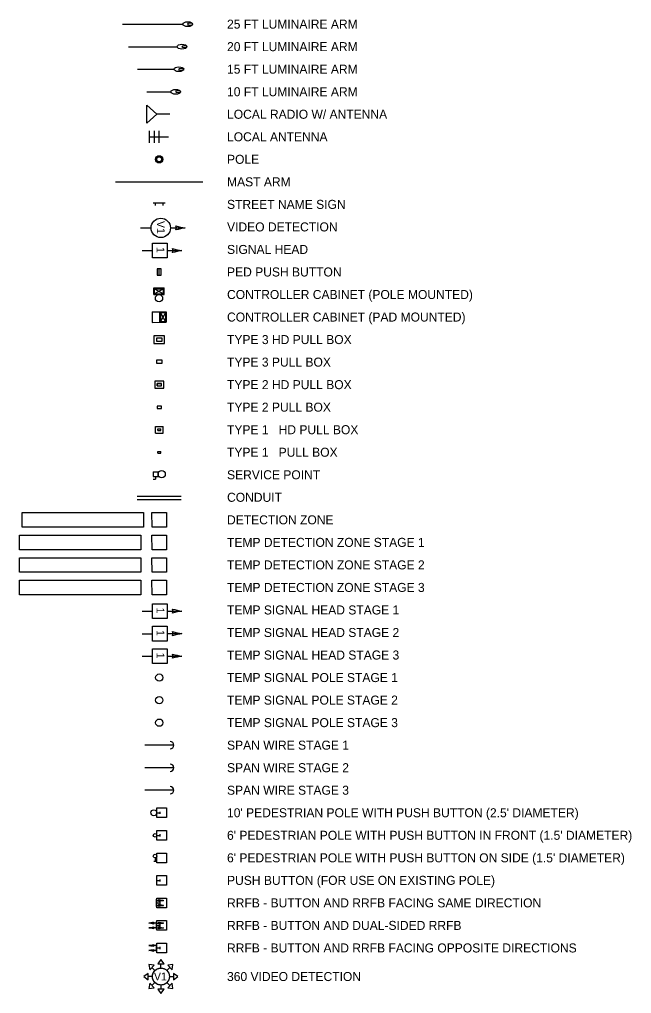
# Model space of a CAD drawing. Extents: x 995948 to 996893, y 1982239 to 1983420.
# Drawn here: x 995947.9 to 996200.4, y 1983017.7 to 1983419.7 of the extents above; entities that cross this region are included whole.
import ezdxf

# ---------------------------------------------------------------- set-up
doc = ezdxf.new("R2010")
doc.units = 0
for name, color, linetype in [('_CIVIL_CONSTRUCTION', 7, 'Continuous'), ('DSN_RDWY_Alignment Annotation', 7, 'Continuous'), ('DSN_ROW_Line-Annotation', 7, 'Continuous'), ('DSN_ROW_Point', 7, 'Continuous'), ('EX_ALIGNMENT', 7, 'Continuous'), ('EX_ROW', 7, 'Continuous'), ('S_CROSS_DRAIN', 7, 'Continuous'), ('S_CURB', 7, 'Continuous'), ('S_DRIVEWAY', 7, 'Continuous'), ('S_EDGE_PAVEMENT', 7, 'Continuous'), ('S_HWY_SYMBOLS', 7, 'Continuous'), ('S_HWY_TEXT', 7, 'Continuous'), ('S_ORTHO_IMAGE', 7, 'Continuous'), ('S_PARKING', 7, 'Continuous'), ('S_PAVEMENT_CROWN', 7, 'Continuous'), ('S_SHOULDER', 7, 'Continuous'), ('S_SIDE_DRAIN', 7, 'Continuous'), ('S_SIDEWALK', 7, 'Continuous'), ('S_WALL', 7, 'Continuous'), ('S_WALL_ANNOT', 7, 'Continuous')]:
    doc.layers.add(name, color=color, linetype=linetype)

msp = doc.modelspace()

# ---------------------------------------------------------------- linework, layer by layer
at = {"layer": '_CIVIL_CONSTRUCTION'}
for p, q in [((995947.87, 1983188.24), (995997.87, 1983188.27)), ((995947.87, 1983182.24), (995947.87, 1983188.24)), ((995997.87, 1983188.27), (995997.87, 1983182.27)), ((995997.87, 1983182.27), (995947.87, 1983182.24))]:
    msp.add_line(p, q, dxfattribs=at)
msp.add_lwpolyline([(996008.55, 1983182.27), (996002.55, 1983182.27), (996002.54, 1983188.27), (996008.54, 1983188.27)], close=True, dxfattribs=at)
at = {"layer": 'DSN_RDWY_Alignment Annotation'}
for p, q in [((995998.43, 1983166.2), (996002.78, 1983166.2)), ((996008.84, 1983166.23), (996014.88, 1983166.23))]:
    msp.add_line(p, q, dxfattribs=at)
msp.add_lwpolyline([(996002.78, 1983163.18), (996002.78, 1983169.25), (996008.84, 1983169.25), (996008.84, 1983163.18)], close=True, dxfattribs=at)
for centre, radius, start, end in [((996009.62, 1983166.22), 1.63, 328.1778, 31.8725), ((996019.28, 1983195.37), 29.47, 253.6787, 261.4168), ((996019.31, 1983137.09), 29.47, 98.6335, 106.3716)]:
    msp.add_arc(centre, radius, start, end, dxfattribs=at)
at = {"layer": 'DSN_ROW_Line-Annotation'}
for p, q in [((996008.84, 1983175.53), (996014.88, 1983175.53)), ((995998.43, 1983175.5), (996002.78, 1983175.5))]:
    msp.add_line(p, q, dxfattribs=at)
msp.add_lwpolyline([(996002.78, 1983172.48), (996002.78, 1983178.55), (996008.84, 1983178.55), (996008.84, 1983172.48)], close=True, dxfattribs=at)
for centre, radius, start, end in [((996009.62, 1983175.52), 1.63, 328.1778, 31.8725), ((996019.28, 1983204.67), 29.47, 253.6787, 261.4168), ((996019.31, 1983146.39), 29.47, 98.6335, 106.3716)]:
    msp.add_arc(centre, radius, start, end, dxfattribs=at)
at = {"layer": 'DSN_ROW_Point'}
for p, q in [((995998.43, 1983156.9), (996002.78, 1983156.9)), ((996008.84, 1983156.93), (996014.88, 1983156.93))]:
    msp.add_line(p, q, dxfattribs=at)
msp.add_lwpolyline([(996002.78, 1983153.88), (996002.78, 1983159.95), (996008.84, 1983159.95), (996008.84, 1983153.88)], close=True, dxfattribs=at)
for centre, radius, start, end in [((996009.62, 1983156.92), 1.63, 328.1778, 31.8725), ((996019.28, 1983186.07), 29.47, 253.6787, 261.4168), ((996019.31, 1983127.79), 29.47, 98.6335, 106.3716)]:
    msp.add_arc(centre, radius, start, end, dxfattribs=at)
at = {"layer": 'EX_ALIGNMENT'}
msp.add_line((996011.54, 1983101.58), (995999.54, 1983101.57), dxfattribs=at)
msp.add_circle((996005.54, 1983129.47), 1.5, dxfattribs=at)
msp.add_arc((996010.04, 1983101.58), 1.5, 270.0252, 90.0252, dxfattribs=at)
at = {"layer": 'EX_ROW'}
msp.add_line((996011.54, 1983110.88), (995999.54, 1983110.87), dxfattribs=at)
msp.add_circle((996005.54, 1983138.77), 1.5, dxfattribs=at)
msp.add_arc((996010.04, 1983110.88), 1.5, 270.0252, 90.0252, dxfattribs=at)
at = {"layer": 'S_CROSS_DRAIN'}
msp.add_lwpolyline([(996004.64, 1983316.79), (996004.64, 1983314.15), (996005.51, 1983314.15), (996005.51, 1983316.79)], close=True, dxfattribs=at)
at = {"layer": 'S_CURB'}
for p, q in [((996002.65, 1983299.03), (996008.39, 1983299.04)), ((996002.65, 1983299.03), (996002.65, 1983294.7)), ((996005.65, 1983299.03), (996005.65, 1983294.7)), ((996005.98, 1983298.7), (996008.06, 1983298.71)), ((996005.98, 1983298.7), (996005.98, 1983295.03)), ((996008.06, 1983295.04), (996005.98, 1983298.7)), ((996008.06, 1983298.68), (996005.98, 1983295.03)), ((996008.06, 1983298.71), (996008.06, 1983295.04)), ((996008.39, 1983299.04), (996008.39, 1983294.71)), ((996002.65, 1983294.7), (996008.39, 1983294.71)), ((996005.98, 1983295.03), (996008.06, 1983295.04))]:
    msp.add_line(p, q, dxfattribs=at)
at = {"layer": 'S_DRIVEWAY'}
for p, q in [((996003.03, 1983233.03), (996003.03, 1983231.03)), ((996003.03, 1983233.03), (996005.03, 1983233.03)), ((996005.03, 1983233.03), (996005.03, 1983231.03)), ((996003.03, 1983231.03), (996005.03, 1983231.03)), ((996003.03, 1983230.03), (996004.03, 1983230.03)), ((996004.03, 1983231.03), (996004.03, 1983230.03)), ((995996.47, 1983222.96), (996014.6, 1983222.97)), ((995996.47, 1983221.64), (996014.6, 1983221.65))]:
    msp.add_line(p, q, dxfattribs=at)
msp.add_circle((996006.53, 1983232.03), 1.5, dxfattribs=at)
at = {"layer": 'S_EDGE_PAVEMENT'}
for p, q in [((995987.49, 1983352.67), (996023.49, 1983352.68)), ((996004.3, 1983056.57), (996004.3, 1983053.57)), ((996004.3, 1983056.07), (996007.32, 1983056.07)), ((996004.3, 1983055.19), (996004.3, 1983054.94)), ((996004.3, 1983055.19), (996004.55, 1983055.19)), ((996004.55, 1983054.94), (996004.3, 1983054.94)), ((996004.55, 1983054.94), (996004.55, 1983055.19)), ((996004.3, 1983054.07), (996007.32, 1983054.07)), ((996004.3, 1983047.27), (996004.3, 1983044.27)), ((996004.3, 1983046.77), (996001.28, 1983046.77)), ((996004.3, 1983044.77), (996001.28, 1983044.77)), ((996004.3, 1983046.77), (996007.32, 1983046.77)), ((996004.3, 1983045.89), (996004.3, 1983045.64)), ((996004.3, 1983045.89), (996004.55, 1983045.89)), ((996004.55, 1983045.64), (996004.3, 1983045.64)), ((996004.3, 1983044.77), (996007.32, 1983044.77)), ((996004.55, 1983045.64), (996004.55, 1983045.89)), ((996004.3, 1983037.47), (996001.28, 1983037.47)), ((996004.3, 1983035.47), (996001.28, 1983035.47)), ((996004.3, 1983037.97), (996004.3, 1983034.97)), ((996004.3, 1983036.59), (996004.3, 1983036.34)), ((996004.3, 1983036.59), (996004.55, 1983036.59)), ((996004.55, 1983036.34), (996004.3, 1983036.34)), ((996004.55, 1983036.34), (996004.55, 1983036.59))]:
    msp.add_line(p, q, dxfattribs=at)
for centre, radius in [((996005.48, 1983361.98), 1.5), ((996005.48, 1983361.98), 1.25), ((996005.48, 1983361.98), 1), ((996005.54, 1983148.07), 1.5), ((996003.3, 1983092.27), 1.25), ((996003.8, 1983082.97), 0.75), ((996003.8, 1983074.42), 0.75)]:
    msp.add_circle(centre, radius, dxfattribs=at)
for centre, radius, start, end in [((996004.68, 1983056.07), 0.814, 328.1778, 31.8725), ((996009.51, 1983070.64), 14.74, 253.6787, 261.4168), ((996009.53, 1983041.5), 14.74, 98.6335, 106.3716), ((996004.68, 1983054.07), 0.814, 328.1778, 31.8725), ((996009.52, 1983068.64), 14.74, 253.6787, 261.4168), ((996009.53, 1983039.5), 14.74, 98.6335, 106.3716), ((995999.06, 1983061.34), 14.74, 278.6335, 286.3716), ((996003.91, 1983046.77), 0.814, 148.1778, 211.8725), ((996004.68, 1983046.77), 0.814, 328.1778, 31.8725), ((996009.51, 1983061.34), 14.74, 253.6787, 261.4168), ((995999.08, 1983032.2), 14.74, 73.6787, 81.4168), ((995999.06, 1983059.34), 14.74, 278.6335, 286.3716), ((995999.08, 1983030.2), 14.74, 73.6787, 81.4168), ((996003.91, 1983044.77), 0.814, 148.1778, 211.8725), ((996009.53, 1983032.2), 14.74, 98.6335, 106.3716), ((996004.68, 1983044.77), 0.814, 328.1778, 31.8725), ((996009.52, 1983059.34), 14.74, 253.6787, 261.4168), ((996009.53, 1983030.2), 14.74, 98.6335, 106.3716), ((995999.06, 1983052.04), 14.74, 278.6335, 286.3716), ((995999.08, 1983022.9), 14.74, 73.6787, 81.4168), ((995999.06, 1983050.04), 14.74, 278.6335, 286.3716), ((995999.08, 1983020.9), 14.74, 73.6787, 81.4168), ((996003.91, 1983037.47), 0.814, 148.1778, 211.8725), ((996003.91, 1983035.47), 0.814, 148.1778, 211.8725)]:
    msp.add_arc(centre, radius, start, end, dxfattribs=at)
at = {"layer": 'S_HWY_SYMBOLS'}
for p, q in [((995947.87, 1983197.54), (995997.87, 1983197.57)), ((995947.87, 1983191.54), (995947.87, 1983197.54)), ((995997.87, 1983197.57), (995997.87, 1983191.57)), ((995997.87, 1983191.57), (995947.87, 1983191.54))]:
    msp.add_line(p, q, dxfattribs=at)
msp.add_lwpolyline([(996008.55, 1983191.57), (996002.55, 1983191.57), (996002.54, 1983197.57), (996008.54, 1983197.57)], close=True, dxfattribs=at)
at = {"layer": 'S_HWY_TEXT'}
for p, q in [((995947.87, 1983206.84), (995997.87, 1983206.87)), ((995947.87, 1983200.84), (995947.87, 1983206.84)), ((995997.87, 1983206.87), (995997.87, 1983200.87)), ((995997.87, 1983200.87), (995947.87, 1983200.84))]:
    msp.add_line(p, q, dxfattribs=at)
msp.add_lwpolyline([(996008.55, 1983200.87), (996002.55, 1983200.87), (996002.54, 1983206.87), (996008.54, 1983206.87)], close=True, dxfattribs=at)
at = {"layer": 'S_ORTHO_IMAGE'}
msp.add_line((996011.54, 1983120.18), (995999.54, 1983120.17), dxfattribs=at)
msp.add_arc((996010.04, 1983120.18), 1.5, 270.0252, 90.0252, dxfattribs=at)
at = {"layer": 'S_PARKING'}
for p, q in [((995949.03, 1983216.15), (995999.03, 1983216.17)), ((995949.03, 1983210.15), (995949.03, 1983216.15)), ((995999.03, 1983216.17), (995999.03, 1983210.17)), ((995999.03, 1983210.17), (995949.03, 1983210.15))]:
    msp.add_line(p, q, dxfattribs=at)
msp.add_lwpolyline([(996008.55, 1983210.17), (996002.55, 1983210.17), (996002.54, 1983216.17), (996008.54, 1983216.17)], close=True, dxfattribs=at)
at = {"layer": 'S_PAVEMENT_CROWN'}
for p, q in [((995997.84, 1983333.68), (996002.17, 1983333.68)), ((996010.17, 1983333.68), (996016.23, 1983333.69)), ((995998.43, 1983324.3), (996002.78, 1983324.3)), ((996008.84, 1983324.33), (996014.88, 1983324.33)), ((996006.22, 1983031.7), (996004.91, 1983029.94)), ((996007.54, 1983029.94), (996006.22, 1983031.7)), ((996003.44, 1983029.33), (996001.27, 1983029.65)), ((996001.27, 1983029.65), (996001.58, 1983027.47)), ((996001.58, 1983027.47), (996003.44, 1983029.33)), ((996003.75, 1983027.17), (996002.51, 1983028.4)), ((996004.91, 1983029.94), (996007.54, 1983029.94)), ((996006.23, 1983028.19), (996006.23, 1983029.94)), ((996008.7, 1983027.16), (996009.94, 1983028.4)), ((996011.18, 1983029.65), (996009.01, 1983029.33)), ((996009.01, 1983029.33), (996010.87, 1983027.47)), ((996010.87, 1983027.47), (996011.18, 1983029.65)), ((996000.98, 1983026), (995999.22, 1983024.69)), ((995999.22, 1983024.69), (996000.98, 1983023.38)), ((996000.98, 1983023.38), (996000.98, 1983026)), ((996002.73, 1983024.69), (996000.98, 1983024.69)), ((996009.73, 1983024.69), (996011.48, 1983024.69)), ((996011.48, 1983026), (996011.48, 1983023.38)), ((996013.24, 1983024.69), (996011.48, 1983026)), ((996011.48, 1983023.38), (996013.24, 1983024.69)), ((996001.59, 1983021.9), (996001.27, 1983019.73)), ((996001.27, 1983019.73), (996003.44, 1983020.05)), ((996003.44, 1983020.05), (996001.59, 1983021.9)), ((996003.75, 1983022.22), (996002.51, 1983020.98)), ((996007.54, 1983019.44), (996004.91, 1983019.44)), ((996004.91, 1983019.44), (996006.23, 1983017.68)), ((996006.23, 1983021.19), (996006.23, 1983019.44)), ((996006.23, 1983017.68), (996007.54, 1983019.44)), ((996008.7, 1983022.21), (996009.94, 1983020.98)), ((996010.87, 1983021.91), (996009.01, 1983020.05)), ((996009.01, 1983020.05), (996011.18, 1983019.73)), ((996011.18, 1983019.73), (996010.87, 1983021.91))]:
    msp.add_line(p, q, dxfattribs=at)
for points in [[(996002.78, 1983321.28), (996002.78, 1983327.35), (996008.84, 1983327.35), (996008.84, 1983321.28)], [(996003.55, 1983026.94), (996003.75, 1983027.17), (996003.97, 1983027.37), (996004.21, 1983027.56), (996004.47, 1983027.72), (996004.74, 1983027.86), (996005.02, 1983027.98), (996005.32, 1983028.07), (996005.61, 1983028.14), (996005.92, 1983028.18), (996006.22, 1983028.19), (996006.53, 1983028.18), (996006.83, 1983028.14), (996007.13, 1983028.07), (996007.42, 1983027.98), (996007.7, 1983027.86), (996007.97, 1983027.72), (996008.23, 1983027.56), (996008.47, 1983027.37), (996008.7, 1983027.16), (996008.91, 1983026.94), (996009.09, 1983026.7), (996009.26, 1983026.44), (996009.4, 1983026.17), (996009.52, 1983025.89), (996009.61, 1983025.6), (996009.67, 1983025.3), (996009.71, 1983025), (996009.73, 1983024.69), (996009.71, 1983024.39), (996009.67, 1983024.08), (996009.61, 1983023.78), (996009.52, 1983023.49), (996009.4, 1983023.21), (996009.26, 1983022.94), (996009.1, 1983022.68), (996008.91, 1983022.44), (996008.7, 1983022.21), (996008.48, 1983022.01), (996008.48, 1983022.01), (996008.24, 1983021.82), (996007.98, 1983021.66), (996007.71, 1983021.52), (996007.43, 1983021.4), (996007.13, 1983021.31), (996006.84, 1983021.24), (996006.53, 1983021.2), (996006.23, 1983021.19), (996005.92, 1983021.2), (996005.62, 1983021.24), (996005.32, 1983021.31), (996005.03, 1983021.4), (996004.75, 1983021.52), (996004.48, 1983021.66), (996004.22, 1983021.82), (996003.98, 1983022.01), (996003.75, 1983022.21), (996003.55, 1983022.44), (996003.36, 1983022.68), (996003.2, 1983022.94), (996003.06, 1983023.21), (996002.94, 1983023.49), (996002.85, 1983023.78), (996002.78, 1983024.08), (996002.74, 1983024.38), (996002.73, 1983024.69), (996002.74, 1983024.99), (996002.78, 1983025.29), (996002.85, 1983025.59), (996002.94, 1983025.88), (996003.05, 1983026.17), (996003.2, 1983026.44), (996003.36, 1983026.69)]]:
    msp.add_lwpolyline(points, close=True, dxfattribs=at)
for centre, radius in [((996006.17, 1983333.68), 4), ((996006.23, 1983024.69), 3.5)]:
    msp.add_circle(centre, radius, dxfattribs=at)
for centre, radius, start, end in [((996010.97, 1983333.68), 1.63, 328.1778, 31.8725), ((996020.63, 1983362.83), 29.47, 253.6787, 261.4168), ((996020.66, 1983304.55), 29.47, 98.6335, 106.3716), ((996009.62, 1983324.32), 1.63, 328.1778, 31.8725), ((996019.28, 1983353.47), 29.47, 253.6787, 261.4168), ((996019.31, 1983295.19), 29.47, 98.6335, 106.3716)]:
    msp.add_arc(centre, radius, start, end, dxfattribs=at)
at = {"layer": 'S_SHOULDER'}
for points in [[(996004.54, 1983094.27), (996008.54, 1983094.27), (996008.55, 1983090.27), (996004.55, 1983090.27)], [(996004.54, 1983084.97), (996008.54, 1983084.97), (996008.55, 1983080.97), (996004.55, 1983080.97)], [(996004.54, 1983075.67), (996008.54, 1983075.67), (996008.55, 1983071.67), (996004.55, 1983071.67)], [(996004.54, 1983066.37), (996008.54, 1983066.37), (996008.55, 1983062.37), (996004.55, 1983062.37)], [(996004.54, 1983057.07), (996008.54, 1983057.07), (996008.55, 1983053.07), (996004.55, 1983053.07)], [(996004.54, 1983047.77), (996008.54, 1983047.77), (996008.55, 1983043.77), (996004.55, 1983043.77)], [(996004.54, 1983038.47), (996008.54, 1983038.47), (996008.55, 1983034.47), (996004.55, 1983034.47)]]:
    msp.add_lwpolyline(points, close=True, dxfattribs=at)
at = {"layer": 'S_SIDE_DRAIN'}
for p, q in [((996007.99, 1983343.87), (996002.99, 1983343.87)), ((996003.99, 1983342.87), (996003.99, 1983343.87)), ((996006.99, 1983343.87), (996006.99, 1983342.87)), ((996007.99, 1983343.87), (996006.99, 1983343.87))]:
    msp.add_line(p, q, dxfattribs=at)
at = {"layer": 'S_SIDEWALK'}
for p, q in [((996007.69, 1983289.2), (996003.35, 1983289.2)), ((996003.35, 1983289.2), (996003.36, 1983285.93)), ((996004.35, 1983288.2), (996004.35, 1983286.93)), ((996006.69, 1983288.2), (996004.35, 1983288.2)), ((996006.69, 1983286.93), (996006.69, 1983288.2)), ((996007.69, 1983285.93), (996007.69, 1983289.2)), ((996003.36, 1983285.93), (996007.69, 1983285.93)), ((996004.35, 1983286.93), (996006.69, 1983286.93)), ((996004.35, 1983279.08), (996004.35, 1983277.81)), ((996006.68, 1983279.08), (996004.35, 1983279.08)), ((996004.35, 1983277.81), (996006.68, 1983277.81)), ((996006.68, 1983277.81), (996006.68, 1983279.08)), ((996007.4, 1983270.43), (996003.65, 1983270.43)), ((996003.65, 1983270.43), (996003.65, 1983267.51)), ((996004.65, 1983268.51), (996004.65, 1983269.43)), ((996004.65, 1983269.43), (996006.4, 1983269.43)), ((996004.65, 1983269.43), (996004.65, 1983268.51)), ((996006.4, 1983269.43), (996004.65, 1983269.43)), ((996004.65, 1983268.51), (996006.4, 1983268.51)), ((996004.65, 1983268.51), (996006.4, 1983268.51)), ((996006.4, 1983268.51), (996006.4, 1983269.43)), ((996006.4, 1983268.51), (996006.4, 1983269.43)), ((996007.4, 1983267.51), (996007.4, 1983270.43)), ((996003.65, 1983267.51), (996007.4, 1983267.51)), ((996004.65, 1983260.13), (996004.65, 1983259.21)), ((996006.4, 1983260.13), (996004.65, 1983260.13)), ((996006.4, 1983259.21), (996006.4, 1983260.13)), ((996004.65, 1983259.21), (996006.4, 1983259.21)), ((996004.55, 1983092.27), (996005.86, 1983092.27)), ((996005.86, 1983091.83), (996005.86, 1983092.71)), ((996005.86, 1983082.53), (996005.86, 1983083.41)), ((996004.55, 1983082.97), (996005.86, 1983082.97)), ((996003.36, 1983072.35), (996004.23, 1983072.35)), ((996003.8, 1983073.67), (996003.8, 1983072.35)), ((996004.55, 1983064.37), (996005.86, 1983064.37)), ((996005.86, 1983063.93), (996005.86, 1983064.81)), ((996004.55, 1983055.07), (996005.86, 1983055.07)), ((996005.86, 1983054.63), (996005.86, 1983055.51)), ((996004.55, 1983045.77), (996005.86, 1983045.77)), ((996005.86, 1983045.33), (996005.86, 1983046.21)), ((996004.55, 1983036.47), (996005.86, 1983036.47)), ((996005.86, 1983036.03), (996005.86, 1983036.91))]:
    msp.add_line(p, q, dxfattribs=at)
msp.add_lwpolyline([(996004.64, 1983314.15), (996006.39, 1983314.15), (996006.39, 1983316.79), (996004.64, 1983316.79)], close=True, dxfattribs=at)
at = {"layer": 'S_WALL'}
for p, q in [((995990.31, 1983417.76), (996015.31, 1983417.77)), ((995992.91, 1983408.46), (996012.91, 1983408.47)), ((995996.62, 1983399.16), (996011.62, 1983399.17)), ((996000.35, 1983389.86), (996010.35, 1983389.87)), ((996000.47, 1983376.85), (996000.47, 1983384.35)), ((996000.47, 1983384.35), (996004.47, 1983380.6)), ((996004.47, 1983380.6), (996000.47, 1983376.85)), ((996009.83, 1983380.6), (996004.47, 1983380.6)), ((996001.4, 1983373.76), (996001.4, 1983368.76)), ((996003.4, 1983373.76), (996003.4, 1983368.76)), ((996005.4, 1983373.76), (996005.4, 1983368.76)), ((996001.4, 1983371.26), (996009.4, 1983371.26)), ((996003.27, 1983306.15), (996003.27, 1983308.89)), ((996003.27, 1983308.89), (996007.6, 1983308.89)), ((996003.6, 1983308.56), (996007.27, 1983308.56)), ((996003.6, 1983306.48), (996003.6, 1983308.56)), ((996007.27, 1983308.56), (996003.6, 1983306.48)), ((996003.62, 1983308.56), (996007.27, 1983306.48)), ((996007.27, 1983306.48), (996007.27, 1983308.56)), ((996007.6, 1983306.15), (996007.6, 1983308.89)), ((996003.27, 1983306.15), (996007.6, 1983306.15)), ((996003.6, 1983306.48), (996007.27, 1983306.48)), ((996003.94, 1983251.73), (996007.12, 1983251.73)), ((996003.94, 1983249), (996003.94, 1983251.73)), ((996003.94, 1983249), (996007.12, 1983249)), ((996004.94, 1983250), (996004.94, 1983250.73)), ((996004.94, 1983250.73), (996006.12, 1983250.73)), ((996004.94, 1983250), (996006.12, 1983250)), ((996006.12, 1983250), (996006.12, 1983250.73)), ((996007.12, 1983249), (996007.12, 1983251.73)), ((996004.94, 1983240.7), (996004.94, 1983241.43)), ((996004.94, 1983241.43), (996006.13, 1983241.43)), ((996004.94, 1983240.7), (996006.13, 1983240.71)), ((996006.13, 1983240.71), (996006.13, 1983241.43))]:
    msp.add_line(p, q, dxfattribs=at)
msp.add_circle((996005.43, 1983304.65), 1.5, dxfattribs=at)
for centre, major_axis in [((996017.31, 1983417.77), (2, 0)), ((996018.31, 1983417.77), (-1, 0)), ((996014.91, 1983408.47), (2, 0)), ((996015.91, 1983408.47), (-1, 0)), ((996013.62, 1983399.17), (2, 0)), ((996014.62, 1983399.17), (-1, 0)), ((996012.35, 1983389.87), (2, 0)), ((996013.35, 1983389.87), (-1, 0))]:
    msp.add_ellipse(centre, major_axis=major_axis, ratio=0.5, dxfattribs=at)

# ---------------------------------------------------------------- texts
at = {"layer": 'DSN_RDWY_Alignment Annotation'}
msp.add_text('1', height=3.25, rotation=270.0252, dxfattribs=at).set_placement((996004.43, 1983167.69))
at = {"layer": 'DSN_ROW_Line-Annotation'}
msp.add_text('1', height=3.25, rotation=270.0252, dxfattribs=at).set_placement((996004.43, 1983176.99))
at = {"layer": 'DSN_ROW_Point'}
msp.add_text('1', height=3.25, rotation=270.0252, dxfattribs=at).set_placement((996004.43, 1983158.39))
at = {"layer": 'S_PAVEMENT_CROWN'}
for s, rotation, p in [('V1', 270.0252, (996004.58, 1983336.56)), ('1', 270.0252, (996004.43, 1983325.79)), ('V1', 0.0252, (996003.35, 1983023.1))]:
    msp.add_text(s, height=3.25, rotation=rotation, dxfattribs=at).set_placement(p)
at = {"layer": 'S_WALL_ANNOT'}
for s, p in [('25 FT LUMINAIRE ARM', (996033.5, 1983415.93)), ('20 FT LUMINAIRE ARM', (996033.5, 1983406.63)), ('15 FT LUMINAIRE ARM', (996033.5, 1983397.33)), ('10 FT LUMINAIRE ARM', (996033.5, 1983388.03)), ('LOCAL RADIO W/ ANTENNA', (996033.5, 1983378.73)), ('LOCAL ANTENNA', (996033.5, 1983369.43)), ('POLE', (996033.5, 1983360.13)), ('MAST ARM', (996033.5, 1983350.83)), ('STREET NAME SIGN', (996033.5, 1983341.53)), ('VIDEO DETECTION', (996033.5, 1983332.23)), ('SIGNAL HEAD', (996033.5, 1983322.93)), ('PED PUSH BUTTON', (996033.5, 1983313.63)), ('CONTROLLER CABINET (POLE MOUNTED)', (996033.5, 1983304.33)), ('CONTROLLER CABINET (PAD MOUNTED)', (996033.5, 1983295.03)), ('TYPE 3 HD PULL BOX', (996033.5, 1983285.73)), ('TYPE 3 PULL BOX', (996033.5, 1983276.43)), ('TYPE 2 HD PULL BOX', (996033.5, 1983267.13)), ('TYPE 2 PULL BOX', (996033.5, 1983257.83)), ('TYPE 1   HD PULL BOX', (996033.5, 1983248.53)), ('TYPE 1   PULL BOX', (996033.5, 1983239.23)), ('SERVICE POINT', (996033.5, 1983229.93)), ('CONDUIT', (996033.5, 1983220.63)), ('DETECTION ZONE', (996033.5, 1983211.33)), ('TEMP DETECTION ZONE STAGE 1', (996033.5, 1983202.03)), ('TEMP DETECTION ZONE STAGE 2', (996033.5, 1983192.73)), ('TEMP DETECTION ZONE STAGE 3', (996033.5, 1983183.43)), ('TEMP SIGNAL HEAD STAGE 1', (996033.5, 1983174.13)), ('TEMP SIGNAL HEAD STAGE 2', (996033.5, 1983164.83)), ('TEMP SIGNAL HEAD STAGE 3', (996033.5, 1983155.53)), ('TEMP SIGNAL POLE STAGE 1', (996033.5, 1983146.23)), ('TEMP SIGNAL POLE STAGE 2', (996033.5, 1983136.93)), ('TEMP SIGNAL POLE STAGE 3', (996033.5, 1983127.63)), ('SPAN WIRE STAGE 1', (996033.5, 1983118.33)), ('SPAN WIRE STAGE 2', (996033.5, 1983109.03)), ('SPAN WIRE STAGE 3', (996033.5, 1983099.73)), ("10' PEDESTRIAN POLE WITH PUSH BUTTON (2.5' DIAMETER)", (996033.5, 1983090.43)), ("6' PEDESTRIAN POLE WITH PUSH BUTTON IN FRONT (1.5' DIAMETER)", (996033.5, 1983081.13)), ("6' PEDESTRIAN POLE WITH PUSH BUTTON ON SIDE (1.5' DIAMETER)", (996033.5, 1983071.83)), ('PUSH BUTTON (FOR USE ON EXISTING POLE)', (996033.5, 1983062.53)), ('RRFB - BUTTON AND RRFB FACING SAME DIRECTION', (996033.5, 1983053.23)), ('RRFB - BUTTON AND DUAL-SIDED RRFB', (996033.5, 1983043.93)), ('RRFB - BUTTON AND RRFB FACING OPPOSITE DIRECTIONS', (996033.5, 1983034.63)), ('360 VIDEO DETECTION', (996033.5, 1983022.83))]:
    msp.add_text(s, height=3.72, dxfattribs=at).set_placement(p)

doc.saveas('drawing.dxf')
